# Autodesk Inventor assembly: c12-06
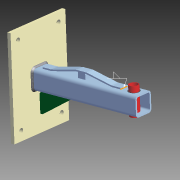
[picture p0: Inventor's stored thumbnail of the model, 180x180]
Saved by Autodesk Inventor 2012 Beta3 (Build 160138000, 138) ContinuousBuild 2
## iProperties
Created: 2011-01
Part Number: c12-06
Document SubType Name: Weldment
Designer: Beta-8540w
Weld Material: Welded Steel Mild
_SolveAssemblyDoc: Frame Generator Solve Assembly
_Version: 15.0.0
Author: Beta-8540w
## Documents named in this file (5)
- C:\Inventor 2012 Essentials\Assemblies\Chapter 12\c12-06.iam
- C:\Inventor 2012 Essentials\Parts\Chapter 12\c12-01.ipt
- C:\Inventor 2012 Essentials\Parts\Chapter 12\c12-02.ipt
- C:\Inventor 2012 Essentials\Assemblies\Chapter 12\Frame\Frame c12-01.iam
- C:\Inventor 2012 Essentials\Parts\Chapter 12\c12-03.ipt
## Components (4 placed, 4 different names)
1. c12-01:1 — Mate:2
2. c12-02:1 — Flush:1
3. Frame c12-01:1 [sub-assembly] — Mate:3
4. c12-03:1 — Mate:1, Mate:2, Mate:3
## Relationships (4: Mate 3, Flush 1)
- Flush:1: c12-02:1
- Mate:1: c12-03:1
- Mate:2: c12-01:1 ↔ c12-03:1
- Mate:3: Frame c12-01:1 ↔ c12-03:1
